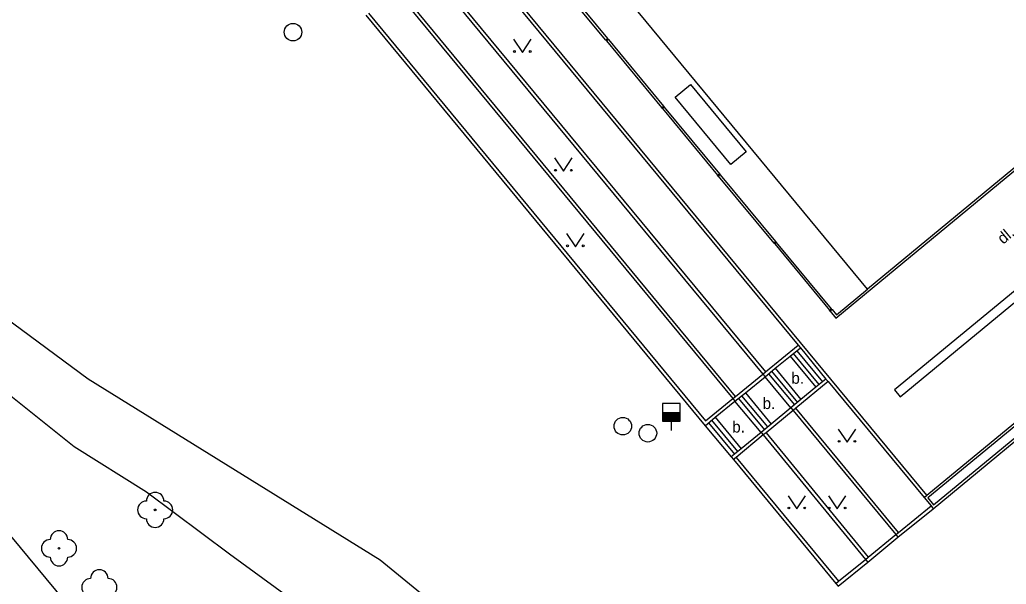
# Model space of a CAD drawing. Extents: x -600391 to -599491, y -1160176 to -1159402.
# Drawn here: x -599752.3 to -599696.1, y -1159909.7 to -1159877.5 of the extents above; entities that cross this region are included whole.
import ezdxf

# ---------------------------------------------------------------- set-up
doc = ezdxf.new("R2010")
doc.units = 0
for name, color, linetype in [('Level 11', 7, 'Continuous'), ('Level 14', 7, 'Continuous'), ('Level 21', 7, 'Continuous'), ('Level 22', 7, 'Continuous'), ('Level 27', 7, 'Continuous'), ('Level 28', 7, 'Continuous'), ('Level 36', 7, 'Continuous'), ('Level 40', 7, 'Continuous'), ('Level 5', 7, 'Continuous')]:
    doc.layers.add(name, color=color, linetype=linetype)

msp = doc.modelspace()

# ---------------------------------------------------------------- linework, layer by layer
at = {"layer": 'Level 11'}
for points in [[(-599700.59, -1159904.64), (-599749.43, -1159845.57)], [(-599727.13, -1159872.83), (-599707.92, -1159896.09)], [(-599729.14, -1159874.49), (-599709.94, -1159897.74)], [(-599728.99, -1159874.37), (-599709.78, -1159897.61)], [(-599718.87, -1159878.7), (-599722.02, -1159874.9)], [(-599721.92, -1159874.82), (-599718.78, -1159878.61)], [(-599711.49, -1159899.01), (-599730.69, -1159875.77)], [(-599730.84, -1159875.89), (-599711.64, -1159899.13)], [(-599732.54, -1159877.29), (-599713.22, -1159900.68)], [(-599732.39, -1159877.17), (-599713.19, -1159900.4), (-599711.64, -1159899.13)], [(-599718.87, -1159878.7), (-599718.78, -1159878.61)], [(-599718.78, -1159878.61), (-599718.73, -1159878.66)], [(-599706.09, -1159894.15), (-599705.77, -1159894.55), (-599686.49, -1159878.61)], [(-599718.82, -1159878.75), (-599718.87, -1159878.7)], [(-599718.73, -1159878.66), (-599718.82, -1159878.75)], [(-599715.69, -1159882.55), (-599718.82, -1159878.75)], [(-599718.73, -1159878.66), (-599715.6, -1159882.47)], [(-599714.93, -1159881.96), (-599714.06, -1159881.24), (-599710.88, -1159885.08), (-599711.75, -1159885.8), (-599714.93, -1159881.96)], [(-599715.69, -1159882.55), (-599715.6, -1159882.47)], [(-599715.64, -1159882.6), (-599715.69, -1159882.55)], [(-599715.55, -1159882.52), (-599715.64, -1159882.6)], [(-599715.6, -1159882.47), (-599715.55, -1159882.52)], [(-599715.55, -1159882.52), (-599712.41, -1159886.32)], [(-599715.64, -1159882.6), (-599712.51, -1159886.4)], [(-599712.51, -1159886.4), (-599712.41, -1159886.32)], [(-599712.47, -1159886.46), (-599712.51, -1159886.4)], [(-599712.37, -1159886.38), (-599712.47, -1159886.46)], [(-599712.47, -1159886.46), (-599709.31, -1159890.27)], [(-599712.41, -1159886.32), (-599712.37, -1159886.38)], [(-599712.37, -1159886.38), (-599709.22, -1159890.19)], [(-599590.61, -1159925.23), (-599623.29, -1159914.37), (-599624.51, -1159916.91), (-599653.71, -1159902.85), (-599687.73, -1159886.52), (-599702.43, -1159898.64), (-599702.12, -1159899.03)], [(-599702.12, -1159899.03), (-599687.66, -1159887.11)], [(-599709.31, -1159890.27), (-599709.22, -1159890.19)], [(-599709.26, -1159890.32), (-599709.31, -1159890.27)], [(-599709.17, -1159890.24), (-599709.26, -1159890.32)], [(-599709.26, -1159890.32), (-599706.14, -1159894.1)], [(-599709.22, -1159890.19), (-599709.17, -1159890.24)], [(-599709.17, -1159890.24), (-599706.04, -1159894.01)], [(-599705.99, -1159894.06), (-599705.74, -1159894.37), (-599703.97, -1159892.9)], [(-599706.14, -1159894.1), (-599706.04, -1159894.01)], [(-599706.09, -1159894.15), (-599706.14, -1159894.1)], [(-599705.99, -1159894.06), (-599706.09, -1159894.15)], [(-599706.04, -1159894.01), (-599705.99, -1159894.06)], [(-599709.78, -1159897.61), (-599707.92, -1159896.09)], [(-599708.38, -1159896.72), (-599707.79, -1159896.24)], [(-599706.73, -1159898.33), (-599708.19, -1159896.57)], [(-599708, -1159896.41), (-599706.54, -1159898.18)], [(-599707.92, -1159896.09), (-599707.79, -1159896.24)], [(-599707.79, -1159896.24), (-599706.35, -1159898.02)], [(-599709.23, -1159897.41), (-599708.38, -1159896.72)], [(-599708.38, -1159896.72), (-599706.92, -1159898.49)], [(-599711.49, -1159899.01), (-599709.94, -1159897.74)], [(-599709.94, -1159897.74), (-599709.78, -1159897.61)], [(-599709.94, -1159897.74), (-599709.81, -1159897.89)], [(-599709.81, -1159897.89), (-599709.23, -1159897.41)], [(-599709.62, -1159897.73), (-599708.14, -1159899.5)], [(-599707.95, -1159899.35), (-599709.43, -1159897.58)], [(-599709.23, -1159897.41), (-599707.77, -1159899.19)], [(-599710.93, -1159898.81), (-599709.81, -1159897.89)], [(-599709.81, -1159897.89), (-599709.8, -1159897.9)], [(-599708.33, -1159899.66), (-599709.8, -1159897.9)], [(-599706.22, -1159898.17), (-599708.05, -1159899.68)], [(-599706.35, -1159898.02), (-599706.92, -1159898.49)], [(-599706.35, -1159898.02), (-599706.22, -1159898.17)], [(-599706.22, -1159898.17), (-599700.74, -1159904.77)], [(-599711.52, -1159899.29), (-599710.93, -1159898.81)], [(-599710.93, -1159898.81), (-599709.46, -1159900.6)], [(-599706.92, -1159898.49), (-599707.77, -1159899.19)], [(-599700.59, -1159904.64), (-599693.38, -1159898.7)], [(-599693.29, -1159898.82), (-599700.53, -1159904.79)], [(-599712.64, -1159900.2), (-599711.52, -1159899.29)], [(-599711.64, -1159899.13), (-599711.49, -1159899.01)], [(-599711.64, -1159899.13), (-599711.52, -1159899.28)], [(-599711.52, -1159899.29), (-599711.52, -1159899.28)], [(-599710.02, -1159901.07), (-599711.52, -1159899.29)], [(-599711.32, -1159899.13), (-599709.83, -1159900.91)], [(-599709.64, -1159900.75), (-599711.13, -1159898.98)], [(-599707.77, -1159899.19), (-599708.33, -1159899.66)], [(-599700.23, -1159905.41), (-599692.43, -1159898.96)], [(-599700.21, -1159905.2), (-599692.57, -1159898.88)], [(-599708.21, -1159899.81), (-599709.75, -1159901.08)], [(-599708.33, -1159899.66), (-599709.46, -1159900.6)], [(-599708.33, -1159899.66), (-599708.21, -1159899.81)], [(-599708.05, -1159899.68), (-599708.21, -1159899.81)], [(-599708.21, -1159899.81), (-599702.36, -1159906.89)], [(-599702.2, -1159906.76), (-599708.05, -1159899.68)], [(-599713.22, -1159900.68), (-599712.64, -1159900.2)], [(-599713.03, -1159900.52), (-599711.54, -1159902.31)], [(-599711.35, -1159902.15), (-599712.84, -1159900.37)], [(-599712.64, -1159900.2), (-599711.17, -1159902)], [(-599713.22, -1159900.68), (-599711.73, -1159902.46)], [(-599710.02, -1159901.07), (-599711.17, -1159902)], [(-599709.46, -1159900.6), (-599710.02, -1159901.07)], [(-599710.02, -1159901.07), (-599709.91, -1159901.21)], [(-599709.75, -1159901.08), (-599709.91, -1159901.21)], [(-599709.75, -1159901.08), (-599703.93, -1159908.17)], [(-599709.91, -1159901.21), (-599711.45, -1159902.49)], [(-599709.91, -1159901.21), (-599704.09, -1159908.3)], [(-599711.17, -1159902), (-599711.73, -1159902.46)], [(-599711.73, -1159902.46), (-599711.6, -1159902.61)], [(-599711.45, -1159902.49), (-599711.6, -1159902.61)], [(-599711.6, -1159902.61), (-599705.78, -1159909.67)], [(-599711.45, -1159902.49), (-599705.62, -1159909.54)], [(-599700.74, -1159904.77), (-599700.59, -1159904.64)], [(-599700.74, -1159904.77), (-599700.35, -1159905.25)], [(-599700.53, -1159904.79), (-599700.21, -1159905.2)], [(-599702.24, -1159907.03), (-599700.23, -1159905.41)], [(-599702.2, -1159906.76), (-599700.35, -1159905.25)], [(-599700.35, -1159905.25), (-599700.23, -1159905.41)], [(-599703.96, -1159908.45), (-599702.24, -1159907.03)], [(-599703.93, -1159908.17), (-599702.36, -1159906.89)], [(-599702.36, -1159906.89), (-599702.2, -1159906.76)], [(-599702.36, -1159906.89), (-599702.24, -1159907.03)], [(-599705.62, -1159909.54), (-599704.09, -1159908.3)], [(-599704.09, -1159908.3), (-599703.93, -1159908.17)], [(-599704.09, -1159908.3), (-599703.96, -1159908.45)], [(-599705.78, -1159909.67), (-599705.65, -1159909.82), (-599703.96, -1159908.45)], [(-599705.78, -1159909.67), (-599705.62, -1159909.54)]]:
    msp.add_lwpolyline(points, dxfattribs=at)
at = {"layer": 'Level 14'}
for points in [[(-599749.74, -1159910.6), (-599758.26, -1159900.32), (-599761.19, -1159897.91), (-599762.33, -1159896.31), (-599765.89, -1159892.16), (-599767.06, -1159891.33)], [(-599749.16, -1159901.88), (-599755.62, -1159896.72)], [(-599745.03, -1159904.47), (-599749.16, -1159901.88)], [(-599740.3, -1159908.01), (-599745.03, -1159904.47)], [(-599734.4, -1159912.31), (-599740.3, -1159908.01)]]:
    msp.add_lwpolyline(points, dxfattribs=at)
at = {"layer": 'Level 21'}
msp.add_lwpolyline([(-599711.45, -1159929.95), (-599716.9, -1159920.48), (-599731.72, -1159908.34), (-599748.36, -1159898.03), (-599772.18, -1159880.4), (-599779.53, -1159872.25), (-599771.12, -1159866.22)], dxfattribs=at)
at = {"layer": 'Level 22'}
for centre in [(-599744.54, -1159905.48), (-599750.02, -1159907.67)]:
    msp.add_circle(centre, 0.05, dxfattribs=at)
for centre, start, end in [((-599744.54, -1159904.98), 0, 180), ((-599745.04, -1159905.48), 90, 270), ((-599744.04, -1159905.48), 270, 90), ((-599744.54, -1159905.98), 180, 0), ((-599750.02, -1159907.17), 0, 180), ((-599750.52, -1159907.67), 90, 270), ((-599749.52, -1159907.67), 270, 90), ((-599750.02, -1159908.17), 180, 0), ((-599747.72, -1159909.39), 0, 180), ((-599748.22, -1159909.89), 90, 270), ((-599747.22, -1159909.89), 270, 90)]:
    msp.add_arc(centre, 0.5, start, end, dxfattribs=at)
at = {"layer": 'Level 27'}
for centre in [(-599736.69, -1159878.25), (-599717.91, -1159900.71), (-599716.48, -1159901.11)]:
    msp.add_circle(centre, 0.5, dxfattribs=at)
at = {"layer": 'Level 28'}
for p, q in [((-599715.65, -1159899.92), (-599714.65, -1159899.92)), ((-599715.65, -1159899.97), (-599714.65, -1159899.97)), ((-599715.65, -1159900.02), (-599714.65, -1159900.02)), ((-599715.65, -1159900.07), (-599714.65, -1159900.07)), ((-599715.65, -1159900.12), (-599714.65, -1159900.12)), ((-599715.65, -1159900.17), (-599714.65, -1159900.17)), ((-599715.65, -1159900.22), (-599714.65, -1159900.22)), ((-599715.65, -1159900.27), (-599714.65, -1159900.27)), ((-599715.65, -1159900.32), (-599714.65, -1159900.32)), ((-599715.65, -1159900.37), (-599714.65, -1159900.37)), ((-599715.15, -1159900.42), (-599715.15, -1159900.95))]:
    msp.add_line(p, q, dxfattribs=at)
msp.add_lwpolyline([(-599715.65, -1159900.42), (-599714.65, -1159900.42), (-599714.65, -1159899.42), (-599715.65, -1159899.42)], close=True, dxfattribs=at)
at = {"layer": 'Level 36'}
for points in [[(-599724.13, -1159878.65), (-599723.63, -1159879.4), (-599723.13, -1159878.65)], [(-599721.79, -1159885.42), (-599721.29, -1159886.17), (-599720.79, -1159885.42)], [(-599721.11, -1159889.73), (-599720.61, -1159890.48), (-599720.11, -1159889.73)], [(-599705.64, -1159900.87), (-599705.14, -1159901.62), (-599704.64, -1159900.87)], [(-599708.5, -1159904.67), (-599708, -1159905.42), (-599707.5, -1159904.67)], [(-599706.2, -1159904.67), (-599705.7, -1159905.42), (-599705.2, -1159904.67)]]:
    msp.add_lwpolyline(points, dxfattribs=at)
for centre in [(-599724.08, -1159879.35), (-599723.181, -1159879.35), (-599721.74, -1159886.12), (-599720.841, -1159886.12), (-599721.06, -1159890.43), (-599720.161, -1159890.43), (-599705.59, -1159901.57), (-599704.691, -1159901.57), (-599708.45, -1159905.37), (-599707.551, -1159905.37), (-599706.15, -1159905.37), (-599705.251, -1159905.37)]:
    msp.add_circle(centre, 0.05, dxfattribs=at)
at = {"layer": 'Level 5'}
for points in [[(-599703.97, -1159892.9), (-599742.7, -1159846.01)], [(-599689.06, -1159880.56), (-599703.97, -1159892.9)]]:
    msp.add_lwpolyline(points, dxfattribs=at)

# ---------------------------------------------------------------- texts
at = {"layer": 'Level 40'}
msp.add_text('dl.', height=0.65, rotation=39.61, dxfattribs=at).set_placement((-599696.25, -1159890.37))
for p in [(-599708.31, -1159898.29), (-599709.95, -1159899.73), (-599711.68, -1159901.07)]:
    msp.add_text('b.', height=0.65, dxfattribs=at).set_placement(p)

doc.saveas('drawing.dxf')
